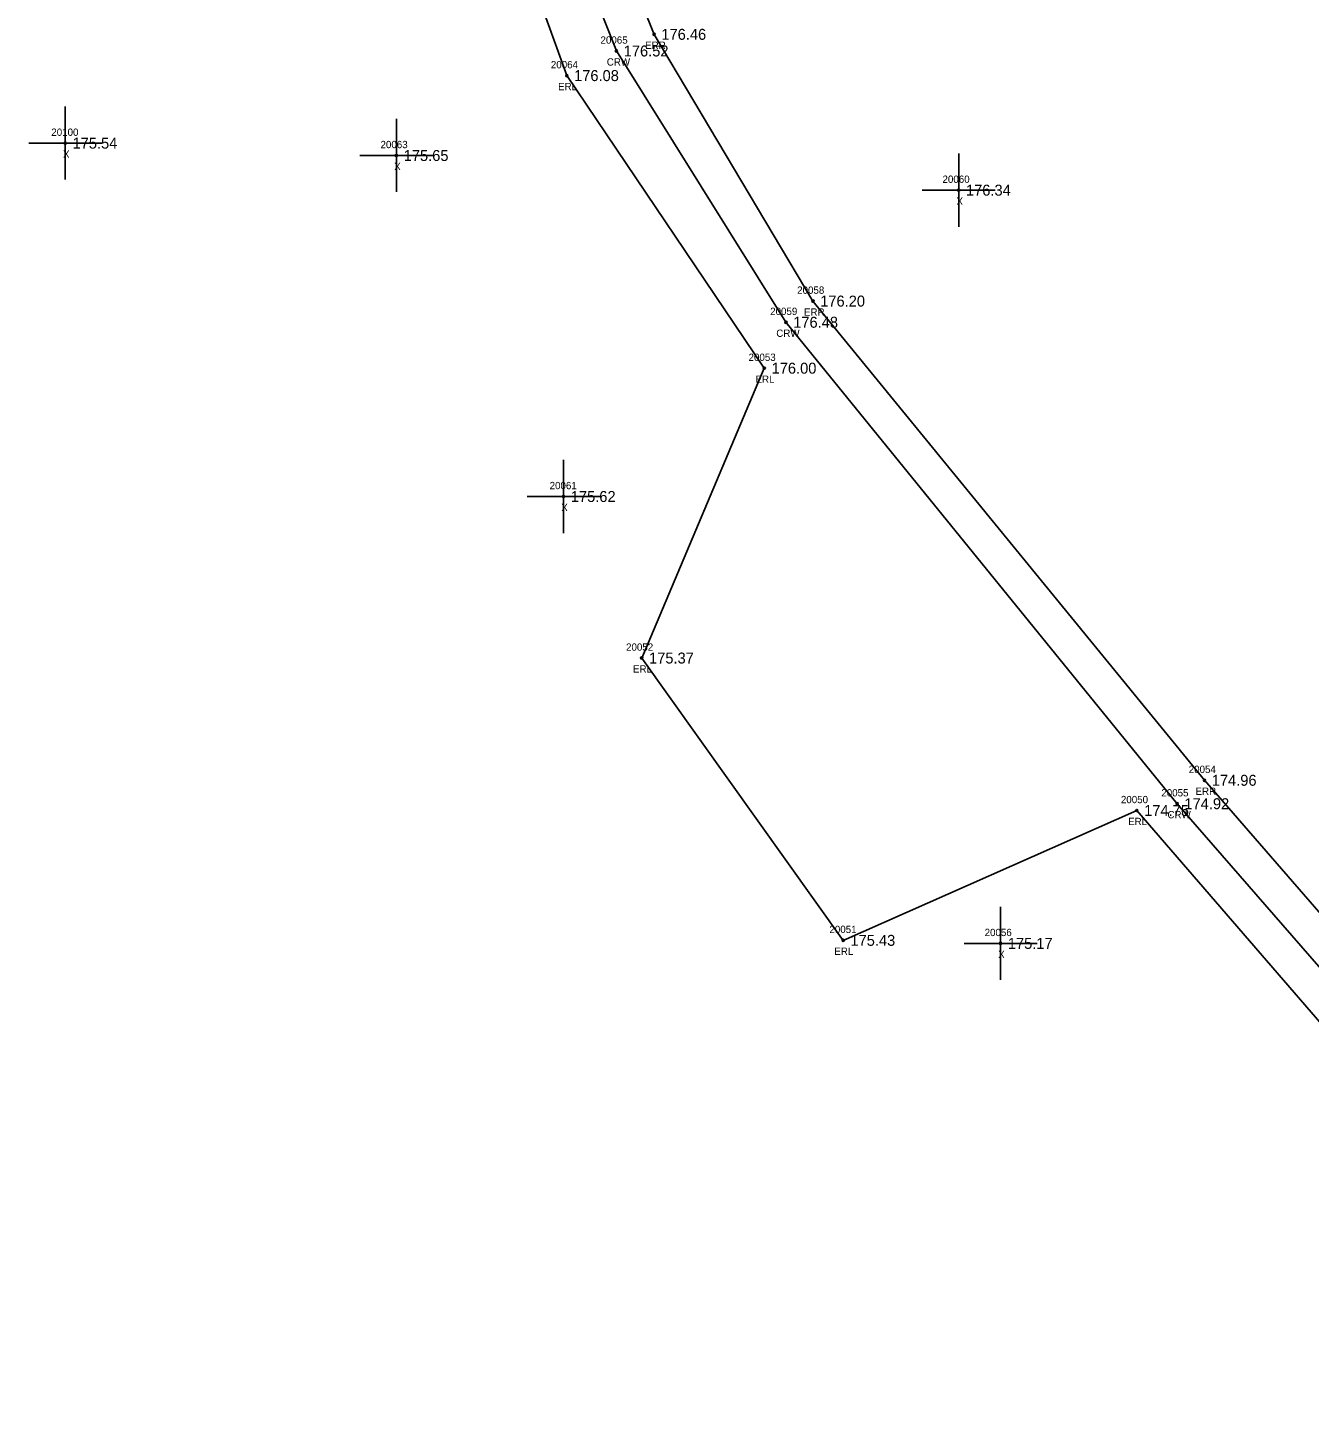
# Model space of a CAD drawing. Extents: x 1970726 to 1971567, y 794829 to 795775.
# Drawn here: x 1970770.6 to 1970946.1, y 795298.6 to 795490.3 of the extents above; entities that cross this region are included whole.
import ezdxf

# ---------------------------------------------------------------- set-up
doc = ezdxf.new("R2010")
doc.units = 0
for name, color, linetype in [('RD_DTM_BkLn1', 7, 'Continuous'), ('RD_EX_Misc', 7, 'Continuous'), ('RD_EX_Misc_txCode', 7, 'Continuous'), ('RD_EX_Road', 7, 'Continuous'), ('RD_EX_Road_txCode', 7, 'Continuous'), ('RD_EX_TX_Misc_ELEV', 7, 'Continuous'), ('RD_EX_TX_Road_ELEV', 7, 'Continuous'), ('RD_HC_Survey_ELEV', 7, 'Continuous'), ('RD_HC_Survey_txCode', 7, 'Continuous'), ('RD_SMD_Locator', 7, 'Continuous')]:
    doc.layers.add(name, color=color, linetype=linetype)

msp = doc.modelspace()

# ---------------------------------------------------------------- linework, layer by layer
at = {"layer": 'RD_DTM_BkLn1'}
msp.add_lwpolyline([(1971548, 794856.6), (1971469.65, 794899.39), (1971398.6, 794938.78), (1971343.49, 794971.52), (1971282.15, 795020.93), (1971214.82, 795076.24), (1971168.26, 795117.15), (1971077.37, 795216.68), (1971014.25, 795285.1), (1970928, 795384.12), (1970874.41, 795450.05), (1970851.19, 795487.2), (1970834.94, 795528.12), (1970822.6, 795571.11), (1970808.56, 795633.3), (1970801.01, 795695.48), (1970787.01, 795762.98)], dxfattribs=at)
at = {"layer": 'RD_EX_Misc'}
for p, q in [((1970775.68, 795469.58), (1970775.68, 795479.58)), ((1970821.05, 795467.89), (1970821.05, 795477.89)), ((1970770.68, 795474.58), (1970780.68, 795474.58)), ((1970898.08, 795463.14), (1970898.08, 795473.14)), ((1970816.05, 795472.89), (1970826.05, 795472.89)), ((1970893.08, 795468.14), (1970903.08, 795468.14)), ((1970843.94, 795421.19), (1970843.94, 795431.19)), ((1970838.94, 795426.19), (1970848.94, 795426.19)), ((1970903.81, 795359.99), (1970903.81, 795369.99)), ((1970898.81, 795364.99), (1970908.81, 795364.99))]:
    msp.add_line(p, q, dxfattribs=at)
at = {"layer": 'RD_EX_Road'}
for points in [[(1971550.5, 794861.13), (1971472.2, 794904.32), (1971401.49, 794943.08), (1971346.58, 794975.73), (1971286.05, 795024.56), (1971217.92, 795079.41), (1971172.76, 795121.06), (1971082.31, 795221.27), (1971017.96, 795288.13), (1970931.75, 795387.33), (1970878.11, 795452.95), (1970856.35, 795489.48), (1970840.29, 795529.45), (1970827.57, 795574.31), (1970814.81, 795635.62), (1970805.04, 795696.13), (1970791.39, 795763.83)], [(1971543.68, 794851.6), (1971507.7, 794872.08), (1971504.76, 794847.96), (1971494.98, 794846.56), (1971488.18, 794883), (1971469.72, 794893.79), (1971395.92, 794934.76), (1971339.47, 794967.38), (1971278.34, 795016.59), (1971212.1, 795072.1), (1971165.04, 795113.96), (1971074.42, 795213.48), (1971010.42, 795281.48), (1970922.49, 795383.19), (1970882.25, 795365.41), (1970854.66, 795404.07), (1970871.45, 795443.76), (1970844.39, 795483.83), (1970828.93, 795526.65), (1970817.76, 795568.61), (1970806.82, 795600.57), (1970787.72, 795602.49), (1970770.58, 795591.56)]]:
    msp.add_lwpolyline(points, dxfattribs=at)
at = {"layer": 'RD_SMD_Locator'}
for centre in [(1970856.35, 795489.48), (1970851.19, 795487.2), (1970844.39, 795483.83), (1970775.68, 795474.58), (1970821.05, 795472.89), (1970898.08, 795468.14), (1970878.11, 795452.95), (1970874.41, 795450.05), (1970871.45, 795443.76), (1970843.94, 795426.19), (1970854.66, 795404.07), (1970931.75, 795387.33), (1970922.49, 795383.19), (1970928, 795384.12), (1970882.25, 795365.41), (1970903.81, 795364.99)]:
    msp.add_circle(centre, 0.15, dxfattribs=at)

# ---------------------------------------------------------------- texts
at = {"layer": 'RD_EX_Misc_txCode'}
for s, p in [('20100', (1970773.77, 795475.58)), ('X', (1970775.37, 795472.58)), ('20063', (1970818.87, 795473.89)), ('X', (1970820.74, 795470.89)), ('20060', (1970895.86, 795469.14)), ('X', (1970897.77, 795466.14)), ('20061', (1970842.04, 795427.19)), ('X', (1970843.63, 795424.19)), ('20056', (1970901.63, 795365.99)), ('X', (1970903.49, 795362.99))]:
    msp.add_text(s, height=1, dxfattribs=at).set_placement(p)
at = {"layer": 'RD_EX_Road_txCode'}
for s, p in [('ERR', (1970855.12, 795487.48)), ('20064', (1970842.21, 795484.83)), ('ERL', (1970843.19, 795481.83)), ('20058', (1970875.95, 795453.95)), ('ERR', (1970876.88, 795450.95)), ('20053', (1970869.29, 795444.76)), ('ERL', (1970870.24, 795441.76)), ('20052', (1970852.51, 795405.07)), ('ERL', (1970853.46, 795402.07)), ('20054', (1970929.59, 795388.33)), ('20050', (1970920.3, 795384.19)), ('ERR', (1970930.52, 795385.33)), ('ERL', (1970921.29, 795381.19)), ('20051', (1970880.37, 795366.41)), ('ERL', (1970881.04, 795363.41))]:
    msp.add_text(s, height=1, dxfattribs=at).set_placement(p)
at = {"layer": 'RD_EX_TX_Misc_ELEV'}
for s, p in [('175.54', (1970776.68, 795473.83)), ('175.65', (1970822.05, 795472.14)), ('176.34', (1970899.08, 795467.39)), ('175.62', (1970844.94, 795425.44)), ('175.17', (1970904.81, 795364.24))]:
    msp.add_text(s, height=1.5, dxfattribs=at).set_placement(p)
at = {"layer": 'RD_EX_TX_Road_ELEV'}
for s, p in [('176.46', (1970857.35, 795488.73)), ('176.08', (1970845.39, 795483.08)), ('176.20', (1970879.11, 795452.2)), ('176.00', (1970872.45, 795443.01)), ('175.37', (1970855.66, 795403.32)), ('174.96', (1970932.75, 795386.58)), ('174.75', (1970923.49, 795382.44)), ('175.43', (1970883.25, 795364.66))]:
    msp.add_text(s, height=1.5, dxfattribs=at).set_placement(p)
at = {"layer": 'RD_HC_Survey_ELEV'}
for s, p in [('176.52', (1970852.19, 795486.45)), ('176.48', (1970875.41, 795449.3)), ('174.92', (1970929, 795383.37))]:
    msp.add_text(s, height=1.5, dxfattribs=at).set_placement(p)
at = {"layer": 'RD_HC_Survey_txCode'}
for s, p in [('20065', (1970849.01, 795488.2)), ('CRW', (1970849.87, 795485.2)), ('20059', (1970872.25, 795451.05)), ('CRW', (1970873.09, 795448.05)), ('20055', (1970925.84, 795385.12)), ('CRW', (1970926.68, 795382.12))]:
    msp.add_text(s, height=1, dxfattribs=at).set_placement(p)

doc.saveas('drawing.dxf')
